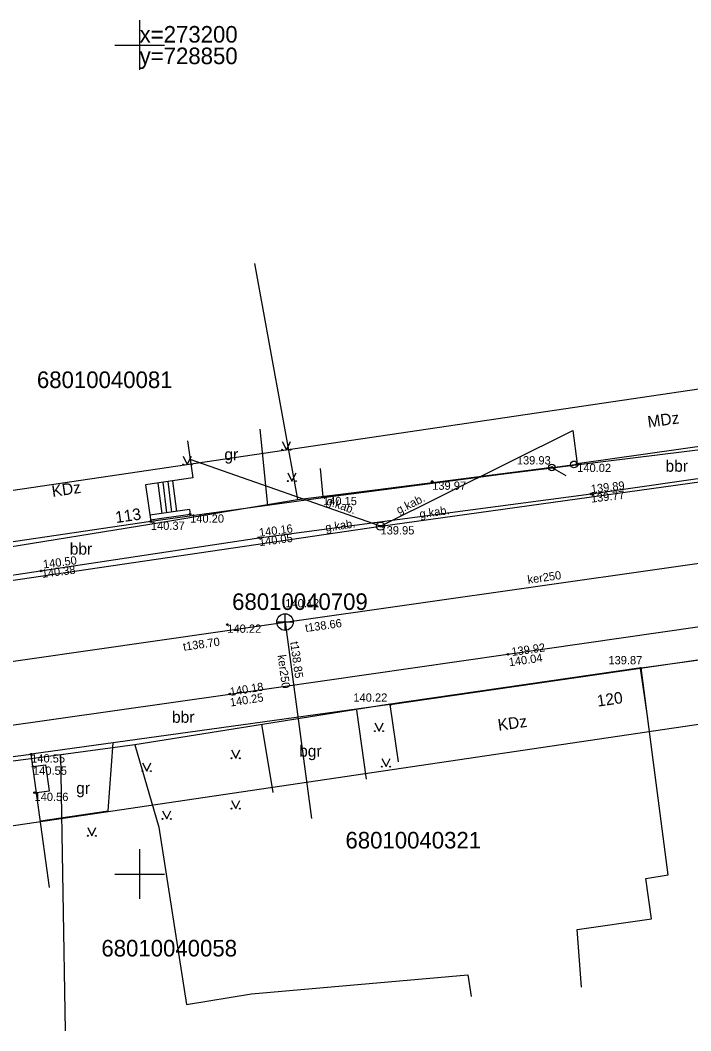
# Model space of a CAD drawing. Extents: x 728785 to 728985, y 273137 to 273208.
# Drawn here: x 728842.8 to 728883.2, y 273140.5 to 273201.5 of the extents above; entities that cross this region are included whole.
import ezdxf

# ---------------------------------------------------------------- set-up
doc = ezdxf.new("R2010")
doc.units = 0
for name, color, linetype in [('APGR_SARK_####_####_#', 7, 'Continuous'), ('BUVE_BDET_####_####_#', 7, 'Continuous'), ('BUVE_EKAS_####_####_#', 7, 'Continuous'), ('BUVE_EKAS_ADRS_TKST_#', 7, 'Continuous'), ('BUVE_EKAS_RAKS_TKST_#', 7, 'Continuous'), ('CELI_CAPM_####_####_#', 7, 'Continuous'), ('CELI_CMAL_####_####_#', 7, 'Continuous'), ('CELI_CSEG_####_TKST_#', 7, 'Continuous'), ('ELEK_ELEM_####_####_#', 7, 'Continuous'), ('ELEK_VADV_ZSPR_####_#', 7, 'Continuous'), ('ELEK_VADV_ZSPR_TKST_#', 7, 'Continuous'), ('GEOD_ELEM_####_####_#', 7, 'Continuous'), ('GEOD_KORD_####_TKST_#', 7, 'Continuous'), ('NORB_ELEM_####_####_#', 7, 'Continuous'), ('NORB_ZOGS_ZSTP_####_#', 7, 'Continuous'), ('RELJ_AATZ_####_TKST_#', 7, 'Continuous'), ('RELJ_ELEM_####_####_#', 7, 'Continuous'), ('ROBZ_KADS_####_TKST_#', 7, 'Continuous'), ('ROBZ_UZMR_####_####_#', 7, 'Continuous'), ('SKAN_ELEM_####_####_#', 7, 'Continuous'), ('SKAN_ELEM_PAST_TKST_#', 7, 'Continuous'), ('SKAN_VADP_PAST_####_#', 7, 'Continuous'), ('SKAN_VADP_PAST_TKST_#', 7, 'Continuous'), ('TERT_ELEM_####_####_#', 7, 'Continuous')]:
    doc.layers.add(name, color=color, linetype=linetype)

msp = doc.modelspace()

# ---------------------------------------------------------------- linework, layer by layer
at = {"layer": 'APGR_SARK_####_####_#'}
for points in [[(728955.084, 273187.77), (728943.86, 273188.14), (728816.642, 273169.324)], [(728957.827, 273167.668), (728945.002, 273168.092), (728819.408, 273149.515)]]:
    msp.add_lwpolyline(points, dxfattribs=at)
at = {"layer": 'BUVE_BDET_####_####_#'}
for p, q in [((728851.1, 273173.585), (728851.333, 273171.744)), ((728851.397, 273173.629), (728851.63, 273171.788)), ((728851.694, 273173.673), (728851.927, 273171.831)), ((728851.991, 273173.716), (728852.224, 273171.875)), ((728853.006, 273171.99), (728850.607, 273171.638)), ((728853.044, 273171.692), (728850.644, 273171.34)), ((728853.006, 273171.99), (728853.044, 273171.692)), ((728843.558, 273156.492), (728844.351, 273156.594)), ((728844.568, 273155.022), (728844.351, 273156.594)), ((728843.775, 273154.92), (728844.568, 273155.022))]:
    msp.add_line(p, q, dxfattribs=at)
at = {"layer": 'BUVE_EKAS_####_####_#'}
for p, q in [((728876.139, 273176.762), (728876.392, 273174.747)), ((728888.427, 273176.436), (728876.392, 273174.747)), ((728852.882, 273176.127), (728853.212, 273173.897)), ((728853.212, 273173.897), (728850.348, 273173.474)), ((728850.348, 273173.474), (728850.675, 273171.26)), ((728850.675, 273171.26), (728840.171, 273169.71)), ((728880.21, 273162.407), (728895.607, 273164.692)), ((728865.117, 273160.219), (728880.21, 273162.407)), ((728880.649, 273159.378), (728880.21, 273162.407)), ((728865.617, 273156.769), (728865.117, 273160.219)), ((728822.792, 273154.55), (728843.456, 273157.227)), ((728844.567, 273149.188), (728843.456, 273157.227))]:
    msp.add_line(p, q, dxfattribs=at)
at = {"layer": 'CELI_CAPM_####_####_#'}
msp.add_line((728828.784, 273157.056), (728855.438, 273160.854), dxfattribs=at)
for points in [[(728857.186, 273170.288), (728877.231, 273172.928), (728915.793, 273178.486), (728920.739, 273179.175), (728935.924, 273181.389)], [(728855.438, 273160.854), (728872.218, 273163.259), (728890.623, 273165.918), (728899.975, 273167.245), (728913.935, 273169.231), (728937.385, 273172.585), (728952.292, 273174.776)], [(728827.643, 273165.823), (728857.186, 273170.288)]]:
    msp.add_lwpolyline(points, dxfattribs=at)
at = {"layer": 'CELI_CMAL_####_####_#'}
for points in [[(728857.73, 273172.238), (728857.263, 273176.84)], [(728876.401, 273174.707), (728861.06, 273172.7), (728850.675, 273171.26)], [(728865.117, 273160.219), (728843.456, 273157.227)], [(728863.084, 273159.891), (728863.662, 273155.727)], [(728857.344, 273159.042), (728858.038, 273154.917)], [(728844.012, 273153.208), (728848.093, 273153.814), (728848.406, 273157.911)]]:
    msp.add_lwpolyline(points, dxfattribs=at)
at = {"layer": 'ELEK_ELEM_####_####_#'}
msp.add_circle((728864.528, 273170.982), 0.25, dxfattribs=at)
at = {"layer": 'ELEK_VADV_ZSPR_####_#'}
for p, q in [((728864.528, 273170.982), (728911.092, 273177.457)), ((728864.528, 273170.982), (728876.139, 273176.762)), ((728864.528, 273170.982), (728853.047, 273175.012)), ((728825.007, 273165.16), (728864.528, 273170.982))]:
    msp.add_line(p, q, dxfattribs=at)
at = {"layer": 'GEOD_ELEM_####_####_#'}
for p, q in [((728850, 273201.5), (728850, 273200)), ((728848.5, 273200), (728850, 273200)), ((728850, 273200), (728850, 273198.5)), ((728850, 273200), (728851.5, 273200)), ((728850, 273151.5), (728850, 273150)), ((728848.5, 273150), (728850, 273150)), ((728850, 273150), (728850, 273148.5)), ((728850, 273150), (728851.5, 273150))]:
    msp.add_line(p, q, dxfattribs=at)
at = {"layer": 'NORB_ELEM_####_####_#'}
msp.add_line((728874.863, 273174.521), (728875.713, 273174.034), dxfattribs=at)
for centre in [(728874.863, 273174.521), (728876.199, 273174.707)]:
    msp.add_circle(centre, 0.202, dxfattribs=at)
at = {"layer": 'NORB_ZOGS_ZSTP_####_#'}
msp.add_lwpolyline([(728874.863, 273174.521), (728861.06, 273172.75), (728860.918, 273174.467)], dxfattribs=at)
at = {"layer": 'RELJ_ELEM_####_####_#'}
for centre in [(728874.863, 273174.521), (728876.392, 273174.747), (728867.647, 273173.675), (728861.06, 273172.75), (728877.231, 273172.928), (728853.044, 273171.692), (728850.675, 273171.26), (728864.528, 273170.982), (728857.186, 273170.288), (728844.055, 273168.285), (728855.288, 273165.05), (728858.768, 273165.198), (728872.218, 273163.259), (728880.21, 273162.407), (728855.438, 273160.854), (728865.117, 273160.219), (728843.456, 273157.227), (728843.569, 273156.486), (728843.658, 273154.903)]:
    msp.add_circle(centre, 0.05, dxfattribs=at)
at = {"layer": 'ROBZ_UZMR_####_####_#'}
for p, q in [((728856.925, 273186.835), (728859.521, 273172.6)), ((728876.334, 273174.678), (728884.725, 273175.712)), ((728859.521, 273172.6), (728876.334, 273174.678)), ((728850.622, 273171.096), (728859.521, 273172.6)), ((728840.383, 273169.447), (728850.622, 273171.096)), ((728880.25, 273162.441), (728895.601, 273164.553)), ((728880.25, 273162.441), (728864.856, 273160.215)), ((728881.879, 273149.951), (728880.25, 273162.441)), ((728864.856, 273160.215), (728849.719, 273157.801)), ((728849.719, 273157.801), (728845.247, 273157.196)), ((728849.719, 273157.801), (728851.167, 273152.82)), ((728843.441, 273156.952), (728818.395, 273153.682)), ((728845.247, 273157.196), (728843.441, 273156.952)), ((728845.537, 273140.545), (728845.247, 273157.196)), ((728851.167, 273152.82), (728852.834, 273142.135)), ((728880.525, 273149.73), (728881.879, 273149.951)), ((728880.866, 273147.291), (728880.525, 273149.73)), ((728876.397, 273146.664), (728880.866, 273147.291)), ((728876.642, 273143.18), (728876.397, 273146.664)), ((728856.743, 273142.771), (728869.789, 273143.923)), ((728869.789, 273143.923), (728870.002, 273142.617)), ((728852.834, 273142.135), (728856.743, 273142.771))]:
    msp.add_line(p, q, dxfattribs=at)
at = {"layer": 'SKAN_ELEM_####_####_#'}
for p, q in [((728858.768, 273164.698), (728858.768, 273165.698)), ((728859.268, 273165.198), (728858.268, 273165.198))]:
    msp.add_line(p, q, dxfattribs=at)
msp.add_circle((728858.768, 273165.198), 0.5, dxfattribs=at)
at = {"layer": 'SKAN_VADP_PAST_####_#'}
for points in [[(728858.768, 273165.198), (728904.501, 273171.712), (728961.386, 273179.575)], [(728790.054, 273155.22), (728804.423, 273157.397), (728858.768, 273165.198)], [(728858.768, 273165.198), (728860.366, 273153.349)]]:
    msp.add_lwpolyline(points, dxfattribs=at)
at = {"layer": 'TERT_ELEM_####_####_#'}
for p, q in [((728858.599, 273176.092), (728858.849, 273175.592)), ((728858.849, 273175.592), (728859.099, 273176.092)), ((728852.62, 273175.196), (728852.87, 273174.696)), ((728852.87, 273174.696), (728853.12, 273175.196)), ((728858.932, 273174.2), (728859.182, 273173.7)), ((728859.182, 273173.7), (728859.432, 273174.2)), ((728864.188, 273159.119), (728864.438, 273158.619)), ((728864.438, 273158.619), (728864.688, 273159.119)), ((728855.547, 273157.483), (728855.797, 273156.983)), ((728855.797, 273156.983), (728856.047, 273157.483)), ((728864.616, 273156.976), (728864.866, 273156.476)), ((728864.866, 273156.476), (728865.116, 273156.976)), ((728850.175, 273156.704), (728850.425, 273156.204)), ((728850.425, 273156.204), (728850.675, 273156.704)), ((728855.547, 273154.444), (728855.797, 273153.944)), ((728855.797, 273153.944), (728856.047, 273154.444)), ((728851.382, 273153.821), (728851.632, 273153.321)), ((728851.632, 273153.321), (728851.882, 273153.821)), ((728846.867, 273152.808), (728847.117, 273152.308)), ((728847.117, 273152.308), (728847.367, 273152.808))]:
    msp.add_line(p, q, dxfattribs=at)
for centre, radius in [((728858.598, 273175.592), 0.028), ((728859.098, 273175.592), 0.0263), ((728852.62, 273174.696), 0.028), ((728853.12, 273174.696), 0.0263), ((728858.932, 273173.699), 0.028), ((728859.432, 273173.699), 0.0263), ((728864.187, 273158.619), 0.028), ((728864.687, 273158.619), 0.0263), ((728855.546, 273156.982), 0.028), ((728856.046, 273156.982), 0.0263), ((728850.175, 273156.203), 0.028), ((728850.675, 273156.203), 0.0263), ((728864.616, 273156.476), 0.028), ((728865.116, 273156.476), 0.0263), ((728855.546, 273153.943), 0.028), ((728856.046, 273153.943), 0.0263), ((728851.381, 273153.32), 0.028), ((728851.881, 273153.32), 0.0263), ((728846.866, 273152.307), 0.028), ((728847.366, 273152.307), 0.0263)]:
    msp.add_circle(centre, radius, dxfattribs=at)

# ---------------------------------------------------------------- texts
at = {"layer": 'BUVE_EKAS_ADRS_TKST_#'}
for s, rotation, p in [('113', 8.39415, (728848.582, 273171.163)), ('120', 8.24858, (728877.632, 273160.09))]:
    msp.add_text(s, height=0.7, rotation=rotation, dxfattribs=at).set_placement(p)
at = {"layer": 'BUVE_EKAS_RAKS_TKST_#'}
for s, rotation, p in [('MDz', 7.98875, (728880.685, 273176.92)), ('KDz', 8.39415, (728844.75, 273172.738)), ('KDz', 7.98875, (728871.654, 273158.637))]:
    msp.add_text(s, height=0.7, rotation=rotation, dxfattribs=at).set_placement(p)
at = {"layer": 'CELI_CSEG_####_TKST_#'}
for s, p in [('gr', (728855.113, 273174.962)), ('bbr', (728881.72, 273174.264)), ('bbr', (728845.786, 273169.265)), ('bbr', (728851.953, 273159.121)), ('bgr', (728859.622, 273157.074)), ('gr', (728846.173, 273154.837))]:
    msp.add_text(s, height=0.7, dxfattribs=at).set_placement(p)
at = {"layer": 'ELEK_VADV_ZSPR_TKST_#'}
for rotation, p in [(26.46493, (728865.632, 273171.699)), (340.65835, (728861.219, 273172.303)), (7.91655, (728866.914, 273171.465)), (8.3802, (728861.235, 273170.648))]:
    msp.add_text('g.kab.', height=0.5, rotation=rotation, dxfattribs=at).set_placement(p)
at = {"layer": 'GEOD_KORD_####_TKST_#'}
for s, p in [('x=273200', (728850, 273200.15)), ('y=728850', (728850, 273198.85))]:
    msp.add_text(s, height=1, dxfattribs=at).set_placement(p)
at = {"layer": 'RELJ_AATZ_####_TKST_#'}
for s, p in [('139.93', (728872.751, 273174.704)), ('140.02', (728876.392, 273174.247)), ('139.97', (728867.647, 273173.175)), ('140.15', (728861.06, 273172.25)), ('140.20', (728853.044, 273171.192)), ('140.37', (728850.675, 273170.76)), ('139.95', (728864.528, 273170.482)), ('140.22', (728855.288, 273164.55)), ('139.87', (728878.275, 273162.649)), ('140.22', (728862.893, 273160.393)), ('140.55', (728843.456, 273156.727)), ('140.55', (728843.569, 273155.986)), ('140.56', (728843.658, 273154.403))]:
    msp.add_text(s, height=0.5, dxfattribs=at).set_placement(p)
for s, rotation, p in [('139.89', 6.62669, (728877.246, 273172.971)), ('139.77', 6.62669, (728877.246, 273172.4)), ('140.16', 7.50254, (728857.234, 273170.343)), ('140.05', 7.50254, (728857.234, 273169.773)), ('140.50', 7.23669, (728844.204, 273168.43)), ('140.38', 7.23669, (728844.129, 273167.864)), ('139.92', 8.05005, (728872.465, 273163.15)), ('140.04', 8.05005, (728872.3, 273162.527)), ('140.18', 9.25431, (728855.484, 273160.741)), ('140.25', 9.25431, (728855.484, 273160.096))]:
    msp.add_text(s, height=0.5, rotation=rotation, dxfattribs=at).set_placement(p)
at = {"layer": 'ROBZ_KADS_####_TKST_#'}
for s, p in [('68010040081', (728843.804, 273179.314)), ('68010040709', (728855.579, 273165.928)), ('68010040321', (728862.415, 273151.541)), ('68010040058', (728847.693, 273145.027))]:
    msp.add_text(s, height=1, dxfattribs=at).set_placement(p)
at = {"layer": 'SKAN_ELEM_PAST_TKST_#'}
msp.add_text('140.12', height=0.5, dxfattribs=at).set_placement((728858.788, 273166.083))
at = {"layer": 'SKAN_VADP_PAST_TKST_#'}
for s, rotation, p in [('ker250', 8.258, (728873.432, 273167.503)), ('t138.66', 8.10642, (728860.014, 273164.591)), ('t138.70', 8.16877, (728852.654, 273163.463)), ('t138.85', 277.68162, (728859.082, 273163.989)), ('ker250', 277.68162, (728858.318, 273163.192))]:
    msp.add_text(s, height=0.5, rotation=rotation, dxfattribs=at).set_placement(p)

doc.saveas('drawing.dxf')
